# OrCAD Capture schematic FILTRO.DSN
size A
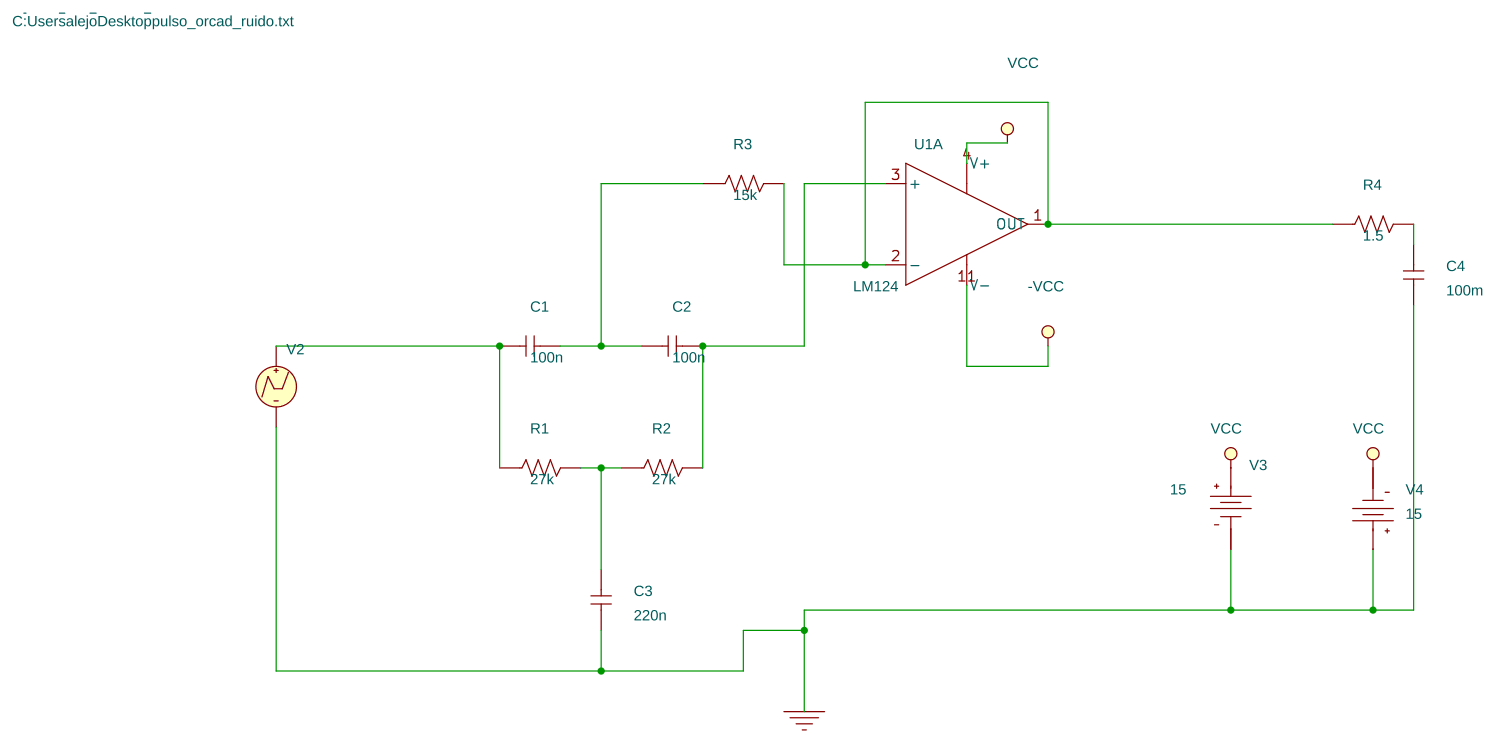
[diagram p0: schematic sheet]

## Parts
C1  100n  [RAD/CK05]
C2  100n  [RAD/CK05]
C3  220n  [RAD/CK05]
C4  100m  [RAD/CK05]
R1  27k  [AX/RC05]
R2  27k  [AX/RC05]
R3  15k  [AX/RC05]
R4  1.5  [AX/RC05]
U1  LM124  [DIP.100/14/W.300/L.800]  (section A)
V2  VPWL_FILE
V3  VDC
V4  VDC

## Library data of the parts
C1-C4 = c
R1-R4 = r
U1 = LM124
V2 = VPWL_FILE: FILE: C:\Users\alejo\Desktop\pulso_orcad_ruido.txt
V3 V4 = VDC: DC: 15

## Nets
-VCC: U1.11(V-) V4.1(-)
VCC: U1.4(V+) V3.0(+)
0: C3.1 C4.1 V2.2(-) V3.1(-) V4.0(+)
N00353: C1.1 R1.1 V2.1(+)
N00516: C3.2 R1.2 R2.1
N00542: C1.2 C2.1 R3.1
N00546: C2.2 R2.2 U1.3(+)
N00932: R3.2 R4.1 U1.1(OUT) U1.2(-)
N01407: C4.2 R4.2
